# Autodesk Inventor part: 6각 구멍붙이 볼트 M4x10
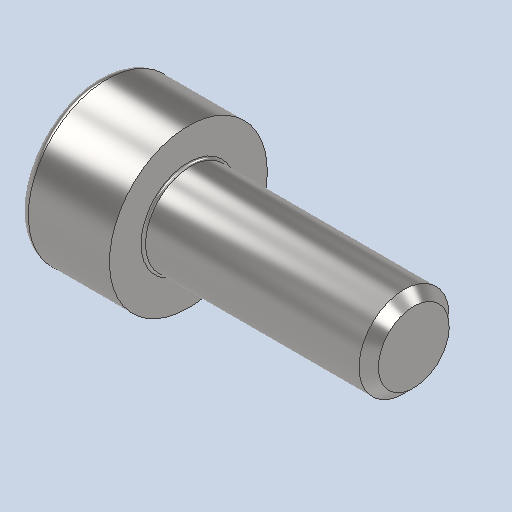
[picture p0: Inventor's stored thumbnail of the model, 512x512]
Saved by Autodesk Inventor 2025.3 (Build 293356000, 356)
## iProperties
Created: 2025-10
Part Number: 6각 구멍붙이 볼트 M4x10
Material: 강철, 연강
Description: 6각머리 태핑 나사
Document SubType Name: Modeling
Designer: USER
Density: 7.85 g/cm^3
Appearance: 기본값
Author: jhkim
Sending System: Autodesk Inventor 2026
Preprocessor: ST-DEVELOPER v20.1
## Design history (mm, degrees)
feature "Solid1"
node "솔리드1"
